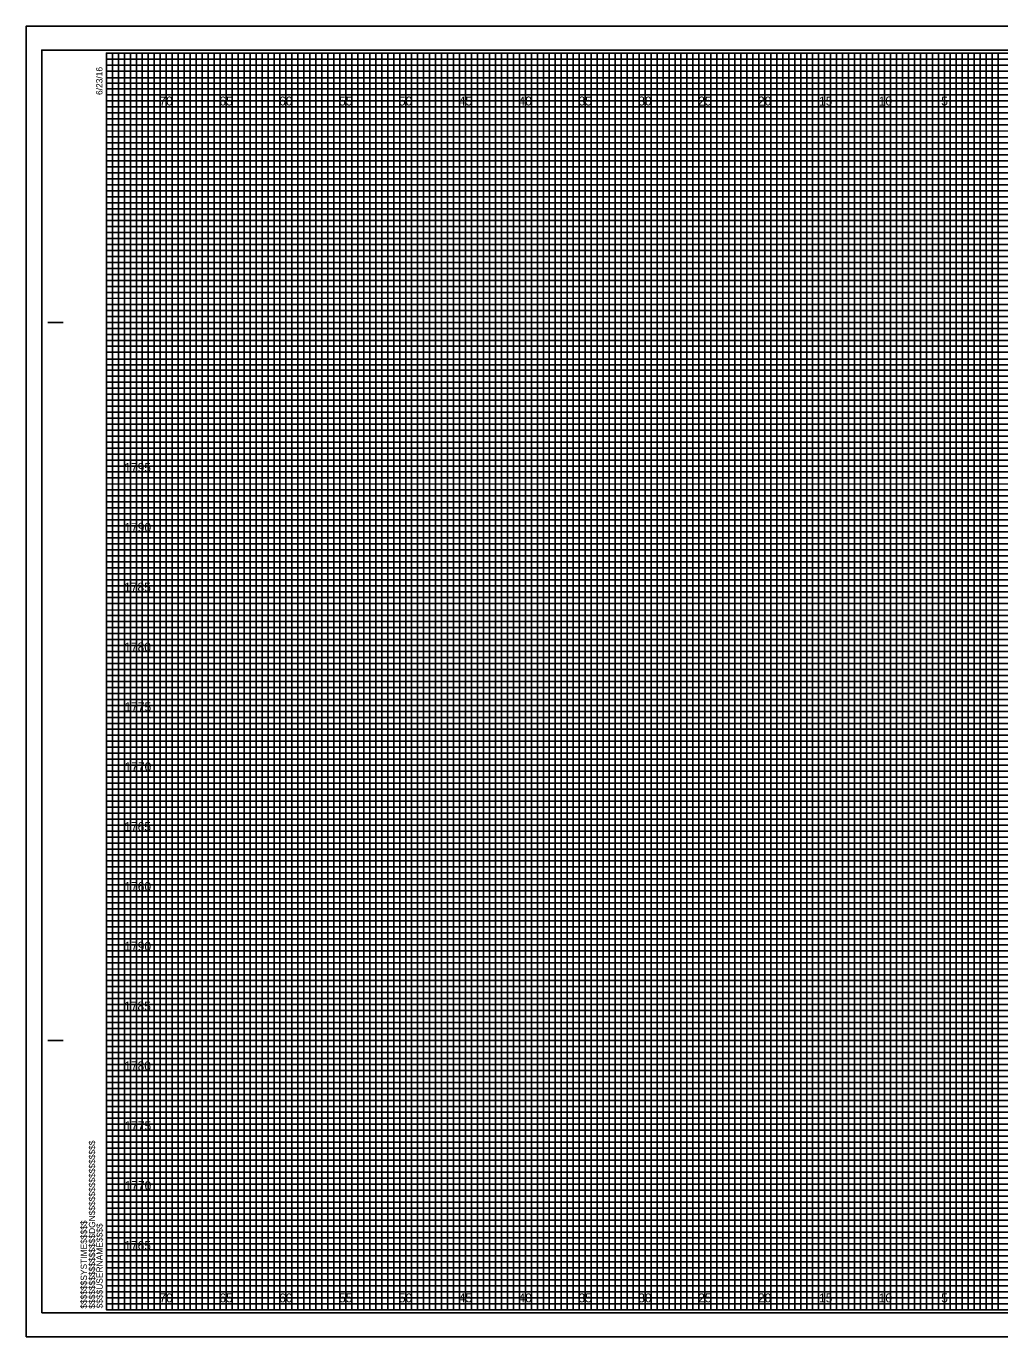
# Model space of a CAD drawing. Extents: x 346 to 514, y -13 to 537.
# Drawn here: x 346 to 427.4, y 97.2 to 206.7 of the extents above; entities that cross this region are included whole.
import ezdxf

# ---------------------------------------------------------------- set-up
doc = ezdxf.new("R2010")
doc.units = 0
for name, color, linetype in [('COGO Default Curve', 7, 'Continuous'), ('Prop Horizontal Alignment', 7, 'Continuous'), ('Prop XS DDE', 7, 'Continuous'), ('Scratch_Level_3', 7, 'Continuous'), ('Sheet Cross Section CELL', 7, 'Continuous'), ('Sheet Cross Section Grid Minor 1 CELL', 7, 'Continuous'), ('Sheet Cross Section Grid Minor 2 CELL', 7, 'Continuous'), ('Sheet Cutting Line CELL', 7, 'Continuous'), ('Sheet DOT Grid CELL', 7, 'Continuous'), ('Sheet Plot Border Inside CELL', 7, 'Continuous'), ('Sheet Plot Border Outside CELL', 7, 'Continuous')]:
    doc.layers.add(name, color=color, linetype=linetype)

msp = doc.modelspace()

# ---------------------------------------------------------------- linework, layer by layer
at = {"layer": 'COGO Default Curve'}
for points in [[(352.75, 204.43), (355.25, 204.43), (355.25, 99.43), (360.25, 99.43), (360.25, 204.43), (365.25, 204.43), (365.25, 99.43), (370.25, 99.43), (370.25, 204.43), (375.25, 204.43), (375.25, 99.43), (380.25, 99.43), (380.25, 204.43), (385.25, 204.43), (385.25, 99.43), (390.25, 99.43), (390.25, 204.43), (395.25, 204.43), (395.25, 99.43), (400.25, 99.43), (400.25, 204.43), (405.25, 204.43), (405.25, 99.43), (410.25, 99.43), (410.25, 204.43), (415.25, 204.43), (415.25, 99.43), (420.25, 99.43), (420.25, 204.43), (425.25, 204.43), (425.25, 99.43), (430.25, 99.43)], [(352.75, 201.93), (490.25, 201.93)], [(352.75, 191.93), (512.75, 191.93), (512.75, 196.93), (352.75, 196.93)], [(352.75, 181.93), (512.75, 181.93), (512.75, 186.93), (352.75, 186.93)], [(352.75, 171.93), (512.75, 171.93), (512.75, 176.93), (352.75, 176.93)], [(352.75, 161.93), (512.75, 161.93), (512.75, 166.93), (352.75, 166.93)], [(352.75, 151.93), (512.75, 151.93), (512.75, 156.93), (352.75, 156.93)], [(352.75, 141.93), (512.75, 141.93), (512.75, 146.93), (352.75, 146.93)], [(352.75, 131.93), (512.75, 131.93), (512.75, 136.93), (352.75, 136.93)], [(352.75, 121.93), (512.75, 121.93), (512.75, 126.93), (352.75, 126.93)], [(352.75, 111.93), (512.75, 111.93), (512.75, 116.93), (352.75, 116.93)], [(352.75, 101.93), (512.75, 101.93), (512.75, 106.93), (352.75, 106.93)]]:
    msp.add_lwpolyline(points, dxfattribs=at)
at = {"layer": 'Prop XS DDE'}
for p, q in [((357.75, 204.43), (352.75, 204.43)), ((357.75, 99.43), (357.75, 204.43)), ((367.75, 204.43), (362.75, 204.43)), ((362.75, 204.43), (362.75, 99.43)), ((367.75, 99.43), (367.75, 204.43)), ((377.75, 204.43), (372.75, 204.43)), ((372.75, 204.43), (372.75, 99.43)), ((377.75, 99.43), (377.75, 204.43)), ((387.75, 204.43), (382.75, 204.43)), ((382.75, 204.43), (382.75, 99.43)), ((387.75, 99.43), (387.75, 204.43)), ((397.75, 204.43), (392.75, 204.43)), ((392.75, 204.43), (392.75, 99.43)), ((397.75, 99.43), (397.75, 204.43)), ((407.75, 204.43), (402.75, 204.43)), ((402.75, 204.43), (402.75, 99.43)), ((407.75, 99.43), (407.75, 204.43)), ((417.75, 204.43), (412.75, 204.43)), ((412.75, 204.43), (412.75, 99.43)), ((417.75, 99.43), (417.75, 204.43)), ((427.75, 204.43), (422.75, 204.43)), ((422.75, 204.43), (422.75, 99.43)), ((362.75, 99.43), (357.75, 99.43)), ((372.75, 99.43), (367.75, 99.43)), ((382.75, 99.43), (377.75, 99.43)), ((392.75, 99.43), (387.75, 99.43)), ((402.75, 99.43), (397.75, 99.43)), ((412.75, 99.43), (407.75, 99.43)), ((422.75, 99.43), (417.75, 99.43))]:
    msp.add_line(p, q, dxfattribs=at)
for points in [[(352.75, 199.43), (512.75, 199.43), (512.75, 194.43), (352.75, 194.43)], [(352.75, 189.43), (512.75, 189.43), (512.75, 184.43), (352.75, 184.43)], [(352.75, 179.43), (512.75, 179.43), (512.75, 174.43), (352.75, 174.43)], [(352.75, 169.43), (512.75, 169.43), (512.75, 164.43), (352.75, 164.43)], [(352.75, 159.43), (512.75, 159.43), (512.75, 154.43), (352.75, 154.43)], [(352.75, 149.43), (512.75, 149.43), (512.75, 144.43), (352.75, 144.43)], [(352.75, 139.43), (512.75, 139.43), (512.75, 134.43), (352.75, 134.43)], [(352.75, 129.43), (512.75, 129.43), (512.75, 124.43), (352.75, 124.43)], [(352.75, 119.43), (512.75, 119.43), (512.75, 114.43), (352.75, 114.43)], [(352.75, 109.43), (512.75, 109.43), (512.75, 104.43), (352.75, 104.43)]]:
    msp.add_lwpolyline(points, dxfattribs=at)
at = {"layer": 'Sheet Cross Section CELL'}
for p, q in [((347.85, 181.93), (349.1, 181.93)), ((347.9, 181.93), (349.15, 181.93)), ((347.85, 121.93), (349.1, 121.93)), ((347.9, 121.93), (349.15, 121.93)), ((352.75, 99.43), (352.75, 99.43)), ((352.75, 99.43), (352.75, 99.43)), ((352.75, 99.43), (352.75, 99.43)), ((352.75, 99.43), (352.75, 99.43)), ((352.75, 99.43), (352.75, 99.43)), ((352.75, 99.43), (352.75, 99.43)), ((352.75, 99.43), (352.75, 99.43))]:
    msp.add_line(p, q, dxfattribs=at)
msp.add_lwpolyline([(512.75, 204.43), (352.75, 204.43), (352.75, 99.43), (512.75, 99.43)], close=True, dxfattribs=at)
at = {"layer": 'Sheet Cross Section Grid Minor 1 CELL'}
for p, q in [((352.75, 203.93), (482.75, 203.93)), ((482.75, 203.42), (352.75, 203.42)), ((352.75, 203.42), (352.75, 202.93)), ((352.75, 202.93), (482.75, 202.93)), ((482.75, 202.37), (352.75, 202.37)), ((352.75, 202.37), (352.75, 201.43)), ((352.75, 201.43), (512.75, 201.43))]:
    msp.add_line(p, q, dxfattribs=at)
for points in [[(352.75, 200.93), (487.75, 200.93), (512.75, 200.93), (512.75, 200.43), (352.75, 200.43)], [(352.75, 199.93), (512.75, 199.93), (512.75, 198.93), (352.75, 198.93)], [(352.75, 198.43), (512.75, 198.43), (512.75, 197.93), (352.75, 197.92)], [(352.75, 197.43), (512.75, 197.43), (512.75, 196.43), (352.75, 196.43)], [(352.75, 195.93), (512.75, 195.93), (512.75, 195.43), (352.75, 195.43)], [(352.75, 194.93), (512.75, 194.93), (512.75, 193.93), (352.75, 193.93)], [(352.75, 193.43), (512.75, 193.43), (512.75, 192.93), (352.75, 192.93)], [(352.75, 192.43), (512.75, 192.43), (512.75, 191.43), (352.75, 191.43)], [(352.75, 190.93), (512.75, 190.93), (512.75, 190.43), (352.75, 190.43)], [(352.75, 189.93), (512.75, 189.93), (512.75, 188.93), (352.75, 188.93)], [(352.75, 188.43), (512.75, 188.43), (512.75, 187.93), (352.75, 187.93)], [(352.75, 187.43), (512.75, 187.43), (512.75, 186.4), (512.75, 185.93), (512.75, 185.43), (352.75, 185.43)], [(352.75, 186.43), (512.75, 186.43), (512.75, 185.93), (352.75, 185.93)], [(352.75, 184.93), (512.75, 184.93), (512.75, 183.93), (352.75, 183.94)], [(352.75, 183.94), (512.75, 183.93), (512.75, 183.43), (352.75, 183.43)], [(352.75, 182.93), (512.75, 182.93), (512.75, 182.43), (352.75, 182.43)], [(352.75, 181.43), (512.75, 181.43), (512.75, 180.93), (352.75, 180.93)], [(352.75, 180.43), (512.75, 180.43), (512.75, 179.93), (352.75, 179.93)], [(352.71, 178.87), (512.75, 178.87), (512.75, 178.37), (352.71, 178.37)], [(352.75, 177.93), (512.75, 177.93), (512.75, 177.43), (352.75, 177.43)], [(352.75, 176.43), (512.75, 176.43), (512.75, 175.93), (352.75, 175.93)], [(352.75, 175.43), (512.75, 175.43), (512.75, 174.93), (352.75, 174.93)], [(352.75, 173.93), (512.75, 173.93), (512.75, 173.43), (352.75, 173.43)], [(352.75, 172.93), (512.75, 172.93), (512.75, 172.43), (352.75, 172.43)], [(352.75, 171.43), (512.75, 171.43), (512.75, 170.93), (352.75, 170.93)], [(352.75, 170.43), (512.75, 170.43), (512.75, 169.93), (352.75, 169.93)], [(352.75, 168.93), (512.75, 168.93), (512.74, 168.42), (352.75, 168.43)], [(352.75, 167.93), (512.75, 167.93), (512.75, 167.43), (352.75, 167.43)], [(352.75, 166.43), (512.75, 166.43), (512.75, 165.93), (352.75, 165.93)], [(352.75, 165.43), (512.75, 165.43), (512.75, 164.93), (352.75, 164.93)], [(352.75, 163.93), (512.75, 163.93), (512.75, 163.43), (352.75, 163.43)], [(352.75, 162.93), (512.75, 162.93), (512.75, 162.43), (352.75, 162.43)], [(352.75, 161.43), (512.75, 161.43), (512.75, 160.93), (352.75, 160.93)], [(352.75, 160.43), (512.75, 160.43), (512.75, 159.93), (352.75, 159.93)], [(352.75, 158.93), (512.75, 158.93), (512.75, 158.43), (352.75, 158.43)], [(352.75, 157.92), (512.78, 157.88), (512.75, 157.43), (352.75, 157.43)], [(352.75, 156.43), (512.75, 156.43), (512.75, 155.93), (352.75, 155.93)], [(352.75, 155.43), (512.75, 155.43), (512.75, 154.93), (352.75, 154.93)], [(352.75, 153.93), (512.75, 153.93), (512.75, 153.43), (352.75, 153.43)], [(352.75, 152.93), (512.75, 152.93), (512.75, 152.43), (352.75, 152.43)], [(352.75, 151.43), (512.75, 151.43), (512.75, 150.93), (352.75, 150.93)], [(352.75, 150.43), (512.75, 150.43), (512.75, 149.93), (352.75, 149.93)], [(352.75, 148.93), (512.75, 148.93), (512.75, 148.43), (352.75, 148.43)], [(352.75, 147.93), (512.75, 147.93), (512.75, 147.43), (352.75, 147.43)], [(352.75, 146.43), (512.75, 146.43), (512.75, 145.93), (352.75, 145.93)], [(352.75, 145.43), (512.75, 145.43), (512.75, 144.93), (352.75, 144.93)], [(352.75, 143.93), (512.75, 143.93), (512.75, 143.43), (352.75, 143.43)], [(352.75, 142.93), (512.75, 142.93), (512.75, 142.43), (352.75, 142.43)], [(352.75, 141.43), (512.75, 141.43), (512.75, 140.93), (352.75, 140.93)], [(352.75, 140.43), (512.75, 140.43), (512.75, 139.93), (352.75, 139.93)], [(352.75, 138.93), (512.75, 138.93), (512.74, 138.42), (352.75, 138.43)], [(352.75, 137.93), (512.75, 137.93), (512.75, 137.43), (352.75, 137.43)], [(352.75, 136.43), (512.75, 136.43), (512.75, 135.93), (352.75, 135.93)], [(352.75, 135.43), (512.75, 135.43), (512.75, 134.93), (352.75, 134.93)], [(352.75, 133.93), (512.75, 133.93), (512.75, 133.43), (352.75, 133.43)], [(352.75, 132.93), (512.75, 132.93), (512.75, 132.43), (352.75, 132.43)], [(352.75, 131.43), (512.75, 131.43), (512.75, 130.93), (352.75, 130.93)], [(352.75, 130.43), (512.75, 130.43), (512.75, 129.93), (352.75, 129.93)], [(352.75, 128.93), (512.75, 128.93), (512.75, 128.43), (352.75, 128.43)], [(352.75, 127.92), (512.78, 127.88), (512.75, 127.43), (352.75, 127.43)], [(352.75, 126.43), (512.75, 126.43), (512.75, 125.93), (352.75, 125.93)], [(352.75, 125.43), (512.75, 125.43), (512.75, 124.93), (352.75, 124.93)], [(352.75, 123.93), (512.75, 123.93), (512.75, 123.43), (352.75, 123.43)], [(352.75, 122.93), (512.75, 122.93), (512.75, 122.43), (352.75, 122.43)], [(352.75, 121.43), (512.75, 121.43), (512.75, 120.93), (352.75, 120.93)], [(352.75, 120.43), (512.75, 120.43), (512.75, 119.93), (352.75, 119.93)], [(352.75, 118.93), (512.75, 118.93), (512.75, 118.43), (352.75, 118.43)], [(352.75, 117.93), (512.75, 117.93), (512.75, 117.43), (352.75, 117.43)], [(352.75, 116.43), (512.75, 116.43), (512.75, 115.93), (352.75, 115.93)], [(352.75, 115.43), (512.75, 115.43), (512.75, 114.93), (352.75, 114.93)], [(352.75, 113.93), (512.75, 113.93), (512.75, 113.43), (352.75, 113.43)], [(352.75, 112.93), (512.75, 112.93), (512.75, 112.43), (352.75, 112.43)], [(352.75, 111.43), (512.75, 111.43), (512.75, 110.93), (352.75, 110.93)], [(352.75, 110.43), (512.75, 110.43), (512.75, 109.93), (352.75, 109.93)], [(352.75, 108.93), (512.75, 108.93), (512.75, 108.43), (352.75, 108.43)], [(352.75, 107.93), (512.75, 107.93), (512.75, 107.43), (352.75, 107.43)], [(352.75, 106.43), (512.75, 106.43), (512.75, 105.93), (352.75, 105.93)], [(352.75, 105.43), (512.75, 105.43), (512.75, 104.93), (352.75, 104.93)], [(352.75, 103.93), (512.75, 103.93), (512.75, 103.43), (352.75, 103.43)], [(352.75, 102.93), (512.75, 102.93), (512.75, 102.43), (352.75, 102.43)], [(352.75, 101.43), (512.75, 101.43), (512.75, 100.93), (352.75, 100.93)], [(352.75, 100.43), (512.75, 100.43), (512.75, 99.93), (352.75, 99.93)]]:
    msp.add_lwpolyline(points, dxfattribs=at)
at = {"layer": 'Sheet Cross Section Grid Minor 2 CELL'}
for points in [[(352.75, 99.43), (353.25, 99.43), (353.25, 204.43), (353.75, 204.43), (353.75, 99.43)], [(353.75, 99.43), (354.25, 99.43), (354.25, 204.43), (354.75, 204.43), (354.75, 99.43)], [(355.25, 99.43), (355.75, 99.43), (355.75, 204.43), (356.25, 204.43), (356.25, 99.43)], [(356.25, 99.43), (356.75, 99.43), (356.75, 204.43), (357.25, 204.43), (357.25, 99.43)], [(357.75, 99.43), (358.25, 99.43), (358.25, 204.43), (358.75, 204.43), (358.75, 99.43)], [(358.75, 99.43), (359.25, 99.43), (359.25, 204.43), (359.75, 204.43), (359.75, 99.43)], [(360.25, 99.43), (360.75, 99.43), (360.75, 204.43), (361.25, 204.43), (361.25, 99.43)], [(361.25, 99.43), (361.75, 99.43), (361.75, 204.43), (362.25, 204.43), (362.25, 99.43)], [(362.75, 99.43), (363.25, 99.43), (363.25, 204.43), (363.75, 204.43), (363.75, 99.43)], [(363.75, 99.43), (364.25, 99.43), (364.25, 204.43), (364.75, 204.43), (364.75, 99.43)], [(365.25, 99.43), (365.75, 99.43), (365.75, 204.43), (366.25, 204.43), (366.25, 99.43)], [(366.25, 99.43), (366.75, 99.43), (366.75, 204.43), (367.25, 204.43), (367.25, 99.43)], [(367.75, 99.43), (368.25, 99.43), (368.25, 204.43), (368.75, 204.43), (368.75, 99.43)], [(368.75, 99.43), (369.25, 99.43), (369.25, 204.43), (369.75, 204.43), (369.75, 99.43)], [(370.25, 99.43), (370.75, 99.43), (370.75, 204.43), (371.25, 204.43), (371.25, 99.43)], [(371.25, 99.43), (371.75, 99.43), (371.75, 204.43), (372.25, 204.43), (372.25, 99.43)], [(372.75, 99.43), (373.25, 99.43), (373.25, 204.43), (373.75, 204.43), (373.75, 99.43)], [(373.75, 99.43), (374.25, 99.43), (374.25, 204.43), (374.75, 204.43), (374.75, 99.43)], [(375.25, 99.43), (375.75, 99.43), (375.75, 204.43), (376.25, 204.43), (376.25, 99.43)], [(376.25, 99.43), (376.75, 99.43), (376.75, 204.43), (377.25, 204.43), (377.25, 99.43)], [(377.75, 99.43), (378.25, 99.43), (378.25, 204.43), (378.75, 204.43), (378.75, 99.43)], [(378.75, 99.43), (379.25, 99.43), (379.25, 204.43), (379.75, 204.43), (379.75, 99.43)], [(380.25, 99.43), (380.75, 99.43), (380.75, 204.43), (381.25, 204.43), (381.25, 99.43)], [(381.25, 99.43), (381.75, 99.43), (381.75, 204.43), (382.25, 204.43), (382.25, 99.43)], [(382.75, 99.43), (383.25, 99.43), (383.25, 204.43), (383.75, 204.43), (383.75, 99.43)], [(383.75, 99.43), (384.25, 99.43), (384.25, 204.43), (384.75, 204.43), (384.75, 99.43)], [(385.25, 99.43), (385.75, 99.43), (385.75, 204.43), (386.25, 204.43), (386.25, 99.43)], [(386.25, 99.43), (386.75, 99.43), (386.75, 204.43), (387.25, 204.43), (387.25, 99.43)], [(387.75, 99.43), (388.25, 99.43), (388.25, 204.43), (388.75, 204.43), (388.75, 99.43)], [(388.75, 99.43), (389.25, 99.43), (389.25, 204.43), (389.75, 204.43), (389.75, 99.43)], [(390.25, 99.43), (390.75, 99.43), (390.75, 204.43), (391.25, 204.43), (391.25, 99.43)], [(391.25, 99.43), (391.75, 99.43), (391.75, 204.43), (392.25, 204.43), (392.25, 99.43)], [(392.75, 99.43), (393.25, 99.43), (393.25, 204.43), (393.75, 204.43), (393.75, 99.43)], [(393.75, 99.43), (394.25, 99.43), (394.25, 204.43), (394.75, 204.43), (394.75, 99.43)], [(395.25, 99.43), (395.75, 99.43), (395.75, 204.43), (396.25, 204.43), (396.25, 99.43)], [(396.25, 99.43), (396.75, 99.43), (396.75, 204.43), (397.25, 204.43), (397.25, 99.43)], [(397.75, 99.43), (398.25, 99.43), (398.25, 204.43), (398.75, 204.43), (398.75, 99.43)], [(398.75, 99.43), (399.25, 99.43), (399.25, 204.43), (399.75, 204.43), (399.75, 99.43)], [(400.25, 99.43), (400.75, 99.43), (400.75, 204.43), (401.25, 204.43), (401.25, 99.43)], [(401.25, 99.43), (401.75, 99.43), (401.75, 204.43), (402.25, 204.43), (402.25, 99.43)], [(402.75, 99.43), (403.25, 99.43), (403.25, 204.43), (403.75, 204.43), (403.75, 99.43)], [(403.75, 99.43), (404.25, 99.43), (404.25, 204.43), (404.75, 204.43), (404.75, 99.43)], [(405.25, 99.43), (405.75, 99.43), (405.75, 204.43), (406.25, 204.43), (406.25, 99.43)], [(406.25, 99.43), (406.75, 99.43), (406.75, 204.43), (407.25, 204.43), (407.25, 99.43)], [(407.75, 99.43), (408.25, 99.43), (408.25, 204.43), (408.75, 204.43), (408.75, 99.43)], [(408.75, 99.43), (409.25, 99.43), (409.25, 204.43), (409.75, 204.43), (409.75, 99.43)], [(410.25, 99.43), (410.75, 99.43), (410.75, 204.43), (411.25, 204.43), (411.25, 99.43)], [(411.25, 99.43), (411.75, 99.43), (411.75, 204.43), (412.25, 204.43), (412.25, 99.43)], [(412.75, 99.43), (413.25, 99.43), (413.25, 204.43), (413.75, 204.43), (413.75, 99.43)], [(413.75, 99.43), (414.25, 99.43), (414.25, 204.43), (414.75, 204.43), (414.75, 99.43)], [(415.25, 99.43), (415.75, 99.43), (415.75, 204.43), (416.25, 204.43), (416.25, 99.43)], [(416.25, 99.43), (416.75, 99.43), (416.75, 204.43), (417.25, 204.43), (417.25, 99.43)], [(417.75, 99.43), (418.25, 99.43), (418.25, 204.43), (418.75, 204.43), (418.75, 99.43)], [(418.75, 99.43), (419.25, 99.43), (419.25, 204.43), (419.75, 204.43), (419.75, 99.43)], [(420.25, 99.43), (420.75, 99.43), (420.75, 204.43), (421.25, 204.43), (421.25, 99.43)], [(421.25, 99.43), (421.75, 99.43), (421.75, 204.43), (422.25, 204.43), (422.25, 99.43)], [(422.75, 99.43), (423.25, 99.43), (423.25, 204.43), (423.75, 204.43), (423.75, 99.43)], [(423.75, 99.43), (424.25, 99.43), (424.25, 204.43), (424.75, 204.43), (424.75, 99.43)], [(425.25, 99.43), (425.75, 99.43), (425.75, 204.43), (426.25, 204.43), (426.25, 99.43)], [(426.25, 99.43), (426.75, 99.43), (426.75, 204.43), (427.25, 204.43), (427.25, 99.43)]]:
    msp.add_lwpolyline(points, dxfattribs=at)
at = {"layer": 'Sheet Cutting Line CELL'}
for p, q in [((514.4, 206.68), (346.05, 206.68)), ((346.05, 206.68), (346.05, 97.18)), ((346.05, 97.18), (514.4, 97.18))]:
    msp.add_line(p, q, dxfattribs=at)
at = {"layer": 'Sheet DOT Grid CELL'}
for p, q in [((357.75, 99.43), (357.75, 204.43)), ((362.75, 99.43), (362.75, 204.43)), ((367.75, 99.43), (367.75, 204.43)), ((372.75, 99.43), (372.75, 204.43)), ((377.75, 99.43), (377.75, 204.43)), ((382.75, 99.43), (382.75, 204.43)), ((387.75, 99.43), (387.75, 204.43)), ((392.75, 99.43), (392.75, 204.43)), ((397.75, 99.43), (397.75, 204.43)), ((402.75, 99.43), (402.75, 204.43)), ((407.75, 99.43), (407.75, 204.43)), ((412.75, 99.43), (412.75, 204.43)), ((417.75, 99.43), (417.75, 204.43)), ((422.75, 99.43), (422.75, 204.43)), ((352.75, 199.43), (512.75, 199.43)), ((352.75, 194.43), (512.75, 194.43)), ((352.75, 189.43), (512.75, 189.43)), ((352.75, 184.43), (512.75, 184.43)), ((352.75, 179.43), (512.75, 179.43)), ((352.75, 174.43), (512.75, 174.43)), ((352.75, 169.43), (512.75, 169.43)), ((352.75, 164.43), (512.75, 164.43)), ((352.75, 159.43), (512.75, 159.43)), ((352.75, 154.43), (512.75, 154.43)), ((352.75, 149.43), (512.75, 149.43)), ((352.75, 144.43), (512.75, 144.43)), ((352.75, 139.43), (512.75, 139.43)), ((352.75, 134.43), (512.75, 134.43)), ((352.75, 129.43), (512.75, 129.43)), ((352.75, 124.43), (512.75, 124.43)), ((352.75, 119.43), (512.75, 119.43)), ((352.75, 114.43), (512.75, 114.43)), ((352.75, 109.43), (512.75, 109.43)), ((352.75, 104.43), (512.75, 104.43))]:
    msp.add_line(p, q, dxfattribs=at)
at = {"layer": 'Sheet Plot Border Inside CELL'}
msp.add_lwpolyline([(347.35, 99.18), (513.95, 99.18), (513.95, 204.68), (347.35, 204.68)], close=True, dxfattribs=at)
at = {"layer": 'Sheet Plot Border Outside CELL'}
msp.add_lwpolyline([(346.05, 97.18), (514.4, 97.18), (514.4, 206.68), (346.05, 206.68)], close=True, dxfattribs=at)

# ---------------------------------------------------------------- texts
at = {"layer": 'Prop Horizontal Alignment'}
for s, p in [('1795', (354.24, 169.43)), ('1790', (354.25, 164.43)), ('1785', (354.23, 159.43)), ('1780', (354.24, 154.43)), ('1775', (354.26, 149.43)), ('1770', (354.27, 144.43)), ('1765', (354.24, 139.43)), ('1760', (354.25, 134.43)), ('1790', (354.25, 129.43)), ('1785', (354.23, 124.43)), ('1780', (354.24, 119.43)), ('1775', (354.26, 114.43)), ('1770', (354.27, 109.43)), ('1765', (354.24, 104.43))]:
    msp.add_text(s, height=0.75, dxfattribs=at).set_placement(p)
at = {"layer": 'Scratch_Level_3'}
for s, p in [('70', (357.18, 200.05)), ('65', (362.19, 200.05)), ('60', (367.18, 200.05)), ('55', (372.19, 200.05)), ('50', (377.18, 200.05)), ('45', (382.19, 200.05)), ('40', (387.18, 200.05)), ('35', (392.19, 200.05)), ('30', (397.18, 200.05)), ('25', (402.19, 200.05)), ('20', (407.18, 200.05)), ('15', (412.28, 200.05)), ('10', (417.27, 200.05)), ('5', (422.49, 200.05)), ('70', (357.18, 100.05)), ('65', (362.19, 100.05)), ('60', (367.18, 100.05)), ('55', (372.19, 100.05)), ('50', (377.18, 100.05)), ('45', (382.19, 100.05)), ('40', (387.18, 100.05)), ('35', (392.19, 100.05)), ('30', (397.18, 100.05)), ('25', (402.19, 100.05)), ('20', (407.18, 100.05)), ('15', (412.28, 100.05)), ('10', (417.27, 100.05)), ('5', (422.49, 100.05))]:
    msp.add_text(s, height=0.75, dxfattribs=at).set_placement(p)
at = {"layer": 'Sheet Cross Section CELL'}
for s, p in [('6/23/16', (352.42, 200.93)), ('$$$$$$$$$$$$$$$$DGN$$$$$$$$$$$$$$$$', (351.81, 99.52)), ('$$$$$$SYSTIME$$$$$', (351.12, 99.52)), ('$$$$USERNAME$$$$', (352.44, 99.54))]:
    msp.add_text(s, height=0.525, rotation=90, dxfattribs=at).set_placement(p)

doc.saveas('drawing.dxf')
